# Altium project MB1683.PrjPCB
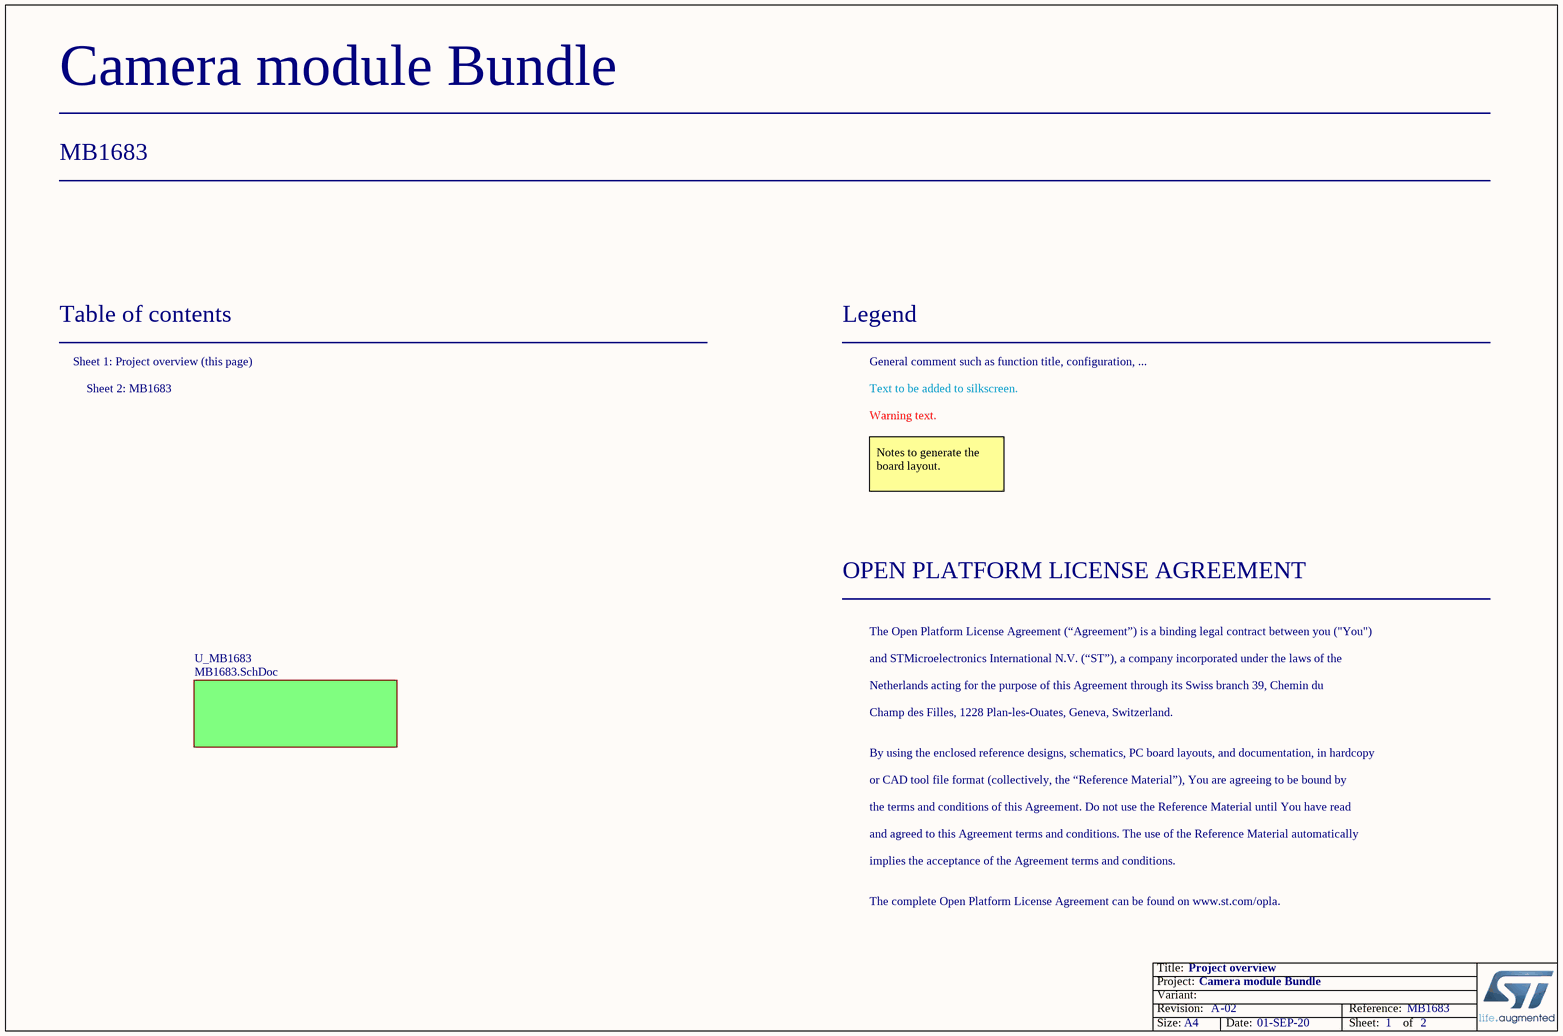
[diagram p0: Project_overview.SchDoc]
Board_Reference: MB1683; Board_PCB_Revision: A; Board_Name: Camera module Bundle; Board_Document_Date: 01-SEP-20; Board_BOM_Revision: 02; Board_Assembly_Revision: 02
2 sheets, 39 parts. Net scope: global (net labels, ports and power ports of the same name join across sheets).
Board file: MB1683.PcbDoc
Sheets:
  Project_overview.SchDoc
    U_MB1683 = MB1683.SchDoc

## Sheet Project_overview.SchDoc: Project overview
size A4; Date: Not used; ApprovedBy: Not used; CheckedBy: Not used; Author: Not used; CompanyName: STMicroelectronics; DrawnBy: Not used; Engineer: Not used; Organization: Not used; Address1: Not used; Address2: Not used; Address3: Not used; Address4: Not used; DocumentNumber: 1; Revision: Not used; SheetNumber: 1; SheetTotal: 2

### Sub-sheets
U_MB1683 = MB1683.SchDoc: no entries

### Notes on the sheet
- Table of contents
- Sheet 1: Project overview (this page)
- Legend
- General comment such as function title, configuration, ...
- Sheet 2: MB1683
- Text to be added to silkscreen.
- Warning text.
- Notes to generate the board layout.
- OPEN PLATFORM LICENSE AGREEMENT
- The Open Platform License Agreement (“Agreement”) is a binding legal contract between you ("You")
- and STMicroelectronics International N.V. (“ST”), a company incorporated under the laws of the
- Netherlands acting for the purpose of this Agreement through its Swiss branch 39, Chemin du
- Champ des Filles, 1228 Plan-les-Ouates, Geneva, Switzerland.
- By using the enclosed reference designs, schematics, PC board layouts, and documentation, in hardcopy
- or CAD tool file format (collectively, the “Reference Material”), You are agreeing to be bound by
- the terms and conditions of this Agreement. Do not use the Reference Material until You have read
- and agreed to this Agreement terms and conditions. The use of the Reference Material automatically
- implies the acceptance of the Agreement terms and conditions.
- The complete Open Platform License Agreement can be found on www.st.com/opla.

## Sheet MB1683.SchDoc: MB1683 TOP
size A4; Date: Not used; ApprovedBy: Not used; CheckedBy: Not used; Author: Not used; CompanyName: STMicroelectronics; DrawnBy: Not used; Engineer: Not used; Organization: Not used; Address1: Not used; Address2: Not used; Address3: Not used; Address4: Not used; DocumentNumber: Not used; Revision: Not used; SheetNumber: 2; SheetTotal: 2
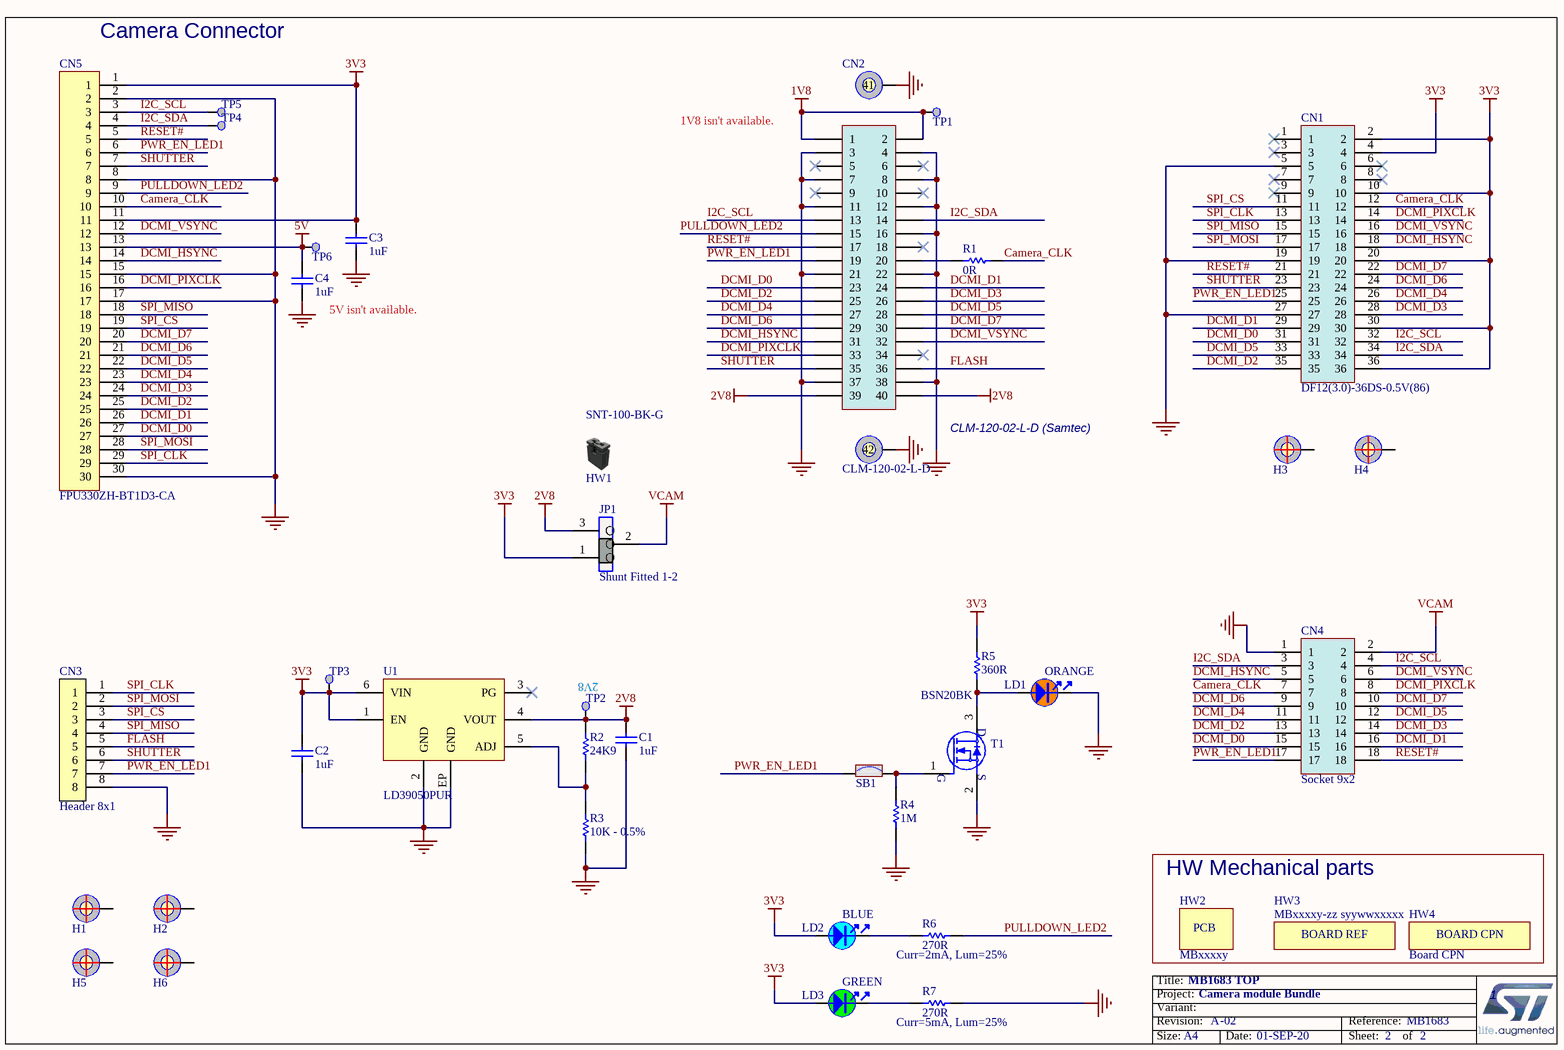
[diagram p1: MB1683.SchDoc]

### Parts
C1  value 1uF  [C0402]  (hidden comment: Capacitor)
C2  value 1uF  [C0402]  (hidden comment: Capacitor)
C3  value 1uF  [C0402]  (hidden comment: Capacitor)
C4  value 1uF  [C0402]  (hidden comment: Capacitor)
CN1  value DF12(3.0)-36DS-0.5V(86)  [CON_HRS_DF12-36DS-0.5V_86]  (hidden comment: DF12-36DS-0.5V)
CN2  value CLM-120-02-L-D  [CON_SAMTEC_CLM-120-02-L-D_Reverse-to-Camera]  (hidden comment: Socket 20x2 CLM_Reverse_for_camera)
CN3  Header 8x1  [CON_SAMTEC_TSW-108-07-X-S]
CN4  Socket 9x2  [CON_SAMTEC_SSW-109-01-X-D]
CN5  FPU330ZH-BT1D3-CA  [CON_TOWNES_FPU330ZH-BT1D3-CA_P050]
H1  POSITION HOLE  [NPTH_350]  (value not drawn)  (no BOM)
H2  POSITION HOLE  [NPTH_350]  (value not drawn)  (no BOM)
H3  POSITION HOLE  [NPTH_350]  (value not drawn)  (no BOM)
H4  POSITION HOLE  [NPTH_350]  (value not drawn)  (no BOM)
H5  POSITION HOLE  [NPTH_350]  (value not drawn)  (no BOM)
H6  POSITION HOLE  [NPTH_350]  (value not drawn)  (no BOM)
HW1  value SNT-100-BK-G  (hidden comment: Shunt Black 2.54mm)  (mechanical)
HW2  value MBxxxxy  (hidden comment: PCB)  (mechanical)
HW3  value MBxxxxy-zz syywwxxxxx  [STICKER_25X9]  (hidden comment: STICKER_BOARD_REF)  (no BOM)
HW4  value Board CPN  [STICKER_25X9]  (hidden comment: STICKER_BOARD_CPN)  (no BOM)
JP1  value Shunt Fitted 1-2  [CON_988-JIUBABA_313103S111116]  (hidden comment: Jumper_Header 3x1 Fitted 1-2)
LD1  value ORANGE  [LED_0603_OSRAM_LO-Q976-PS-25_ORANGE_1A2K_H0P8]  (hidden comment: LED_orange)
LD2  value BLUE  [LED_0603_VISHAY_VLMB1300-GS08_BLUE_1A2K_H0P8]  (hidden comment: LED_blue)
LD3  value GREEN  [LED_0603_VISHAY_VLMTG1300-GS08_GREEN_1A2K_H0P8]  (hidden comment: LED_green)
R1  value 0R  [R0402]  (hidden comment: Resistor)
R2  value 24K9  [R0402]  (hidden comment: Resistor)
R3  value 10K - 0.5%  [R0402]  (hidden comment: Resistor)
R4  value 1M  [R0402]  (hidden comment: Resistor)
R5  value 360R  [R0402]  (hidden comment: Resistor)
R6  value 270R  [R0402]  (hidden comment: Resistor)
R7  value 270R  [R0402]  (hidden comment: Resistor)
SB1  SB_ON  [SOLDER-BRIDGE_R0402-0R]  (value not drawn)
T1  value BSN20BK  [MOS_SOT23]  (hidden comment: BSN20)
TP1  Test Point  [TP_SMD_1MM]  (value not drawn)  (no BOM)
TP2  Test Point  [TP_SMD_1MM]  (value not drawn)  (no BOM)
TP3  Test Point  [TP_SMD_1MM]  (value not drawn)  (no BOM)
TP4  Test Point  [TP_SMD_1MM]  (value not drawn)  (no BOM)
TP5  Test Point  [TP_SMD_1MM]  (value not drawn)  (no BOM)
TP6  Test Point  [TP_SMD_1MM]  (value not drawn)  (no BOM)
U1  LD39050PUR  [ICC_DFN6-EPAD_3X3_P095]

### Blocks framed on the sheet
HW Mechanical parts: HW2-HW4

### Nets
1V8: CN2.1 CN2.2 TP1.1
2V8: C1.2 CN2.39 CN2.40 JP1.3 R2.2 TP2.1 U1.4(VOUT)
3V3: C2.2 C3.2 CN1.2 CN1.4 CN1.10 CN1.20 CN1.30 CN1.36 CN5.1 CN5.11 JP1.1 LD2.1 LD3.1 R5.2 TP3.1 U1.1(EN) U1.6(VIN)
5V: C4.2 CN5.13 TP6.1
GND: C1.1 C2.1 C3.1 C4.1 CN1.5 CN1.19 CN1.27 CN2.3 CN2.4 CN2.7 CN2.8 CN2.11 CN2.12 CN2.16 CN2.21 CN2.22 CN2.37 CN2.38 CN2.41 CN2.42 CN3.8 CN4.1 CN5.2 CN5.8 CN5.15 CN5.17 CN5.30 LD1.2 R3.1 R4.2 R7.2 T1.2(S) U1.2(GND) U1.EP(GND)
VCAM: CN4.2 JP1.2
Camera_CLK: CN1.12 CN4.7 CN5.10 R1.2
DCMI_D0: CN1.31 CN2.23 CN4.15 CN5.27
DCMI_D1: CN1.29 CN2.24 CN4.16 CN5.26
DCMI_D2: CN1.35 CN2.25 CN4.13 CN5.25
DCMI_D3: CN1.28 CN2.26 CN4.14 CN5.24
DCMI_D4: CN1.26 CN2.27 CN4.11 CN5.23
DCMI_D5: CN1.33 CN2.28 CN4.12 CN5.22
DCMI_D6: CN1.24 CN2.29 CN4.9 CN5.21
DCMI_D7: CN1.22 CN2.30 CN4.10 CN5.20
DCMI_HSYNC: CN1.18 CN2.31 CN4.5 CN5.14
DCMI_PIXCLK: CN1.14 CN2.33 CN4.8 CN5.16
DCMI_VSYNC: CN1.16 CN2.32 CN4.6 CN5.12
FLASH: CN2.36 CN3.5
I2C_SCL: CN1.32 CN2.13 CN4.4 CN5.3 TP5.1
I2C_SDA: CN1.34 CN2.14 CN4.3 CN5.4 TP4.1
PULLDOWN_LED2: CN2.15 CN5.9 R6.2
PWR_EN_LED1: CN1.25 CN2.19 CN3.7 CN4.17 CN5.6 SB1.1
RESET#: CN1.21 CN2.17 CN4.18 CN5.5
SHUTTER: CN1.23 CN2.35 CN3.6 CN5.7
SPI_CLK: CN1.13 CN3.1 CN5.29
SPI_CS: CN1.11 CN3.3 CN5.19
SPI_MISO: CN1.15 CN3.4 CN5.18
SPI_MOSI: CN1.17 CN3.2 CN5.28
NetCN2_20: CN2.20 R1.1
NetLD1_1: LD1.1 R5.1 T1.3(D)
NetLD2_2: LD2.2 R6.1
NetLD3_2: LD3.2 R7.1
NetR2_1: R2.1 R3.2 U1.5(ADJ)
NetR4_1: R4.1 SB1.2 T1.1(G)

Not connected (* = marked no-connect by the designer): CN1 1* 3* 6* 7* 8* 9*; CN2 5* 6* 9* 10* 18* 34*; H1 1; H2 1; H3 1; H4 1; H5 1; H6 1; U1 3(PG)*

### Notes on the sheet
- (near CN5) Camera Connector
- 1V8 isn't available.
- (near C4) 5V isn't available.
- (near CN2) CLM-120-02-L-D (Samtec)
- (near TP2) 2V8
- (near R6) Curr=2mA, Lum=25%
- 1
- (near R7) Curr=5mA, Lum=25%

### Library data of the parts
C1-C4 = MCD-01722: Capacitor, MLCC, 1uF, 10V, X5R, +/-10%, 0402, T=0.5mm; Manufacturer_Part_Number: CC0402KRX5R6BB105; Manufacturer: YAGEO; Alternate_Manufacturer_Part_Number: GCM155R71C104KA55D; Alternate_Manufacturer: MURATA; ECCN_US: EAR99; ECCN_EU: NEC; Provided_By: SUBCO
CN1 = MCD-02260: Receptacle, 18x2, 0.5mm, Straight,SMT, height 2.7mm, H=3.0MM; Part_Preference: Recommended; Part_Type: Connector; Manufacturer: HIROSE
CN2 = MCD-00138: Socket, 20x2, 1.0mm, VR, SMT, Height 2.26mm. Symbol & Footprint dedicated to MB1183 & MB1379 camera modules (not in line with Samtec datasheet); Part_Type: Connector; Provided_By: SUBCO; ECCN_US: EAR99; ECCN_EU: NEC
CN3 = MCD-00239: Header, 8x1, 2,54mm, VR, TH, Height 5.84mm/2.54mm; Part_Type: Connector; Manufacturer_Part_Number: TSW-108-07-G-S; Manufacturer: SAMTEC; Provided_By: SUBCO
CN4 = MCD-02157: Socket, 9x2, 2.54mm, VR, TH, Height 8.51mm/2.64mm, Standard insertion force.; Part_Type: Connector; Manufacturer_Part_Number: SSW-109-01-G-D; Manufacturer: SAMTEC; Order_Code_RS: 765-5717; Provided_By: SUBCO
CN5 = MCD-00326: Connector FFC/FPC ZIF 0.5mm 30 pins, Lower Contacts; Manufacturer: TOWNES; Provided_By: SUBCO
H1-H6 = MCD-01368: POSITION HOLE C3R5D3R5; Part_Type: Mechanical
HW1 = MCD-00043: SHUNT 2.54mm BLACK; Part_Type: Mechanical; Manufacturer: SAMTEC; Alternate_Manufacturer_Part_Number: 316102S111A; Alternate_Manufacturer: JIUBABA; Provided_By: SUBCO
HW2 = MCD-00216: PCB, xxxx for PCB number, Y for PCB revision; Part_Type: Mechanical; Provided_By: SUBCO
HW3 = MCD-00235: Sticker to mention board reference + serial number; Part_Type: Mechanical; Provided_By: SUBCO
HW4 = MCD-00547: Sticker to mention board CPN code; Part_Type: Mechanical; Provided_By: SUBCO
JP1 = MCD-01656: Header 3x1, 2.54mm, VR, TH, height 6 mm / 3 mm, total 11.6mm - Shunt Fitted 1-2 by default; Part_Type: Connector; Manufacturer_Part_Number: 313103S111116; Manufacturer: JIUBABA; Provided_By: SUBCO
LD1 = MCD-00590: LED Orange, 0603 SMD, Forward Voltage Min=1.6V, Max=2.4V; Part_Type: Display; Manufacturer_Part_Number: LO Q976-PS-25; Manufacturer: OSRAM OPTO SEMICONDUCTORS; Alternate_Manufacturer_Part_Number: VLMO1300-GS08; Alternate_Manufacturer: VISHAY SEMICONDUCTOR OPTO DIVISION; Provided_By: SUBCO
LD2 = MCD-00585: LED Blue, 0603 SMD, Forward Voltage Min=2,8V, Max=3,8V; Part_Type: Display; Manufacturer_Part_Number: LB Q39G-L2OO-35-1; Manufacturer: OSRAM OPTO SEMICONDUCTORS; Alternate_Manufacturer_Part_Number: 19-217-BHC-ZL1M2RY-3T-V4; Alternate_Manufacturer: EVERLIGHT; Order_Code_RS: 9148643; Provided_By: SUBCO
LD3 = MCD-00588: LED Green, 0603 SMD, Forward Voltage Typ=2V, Max=2.5V; Part_Type: Display; Manufacturer_Part_Number: LG Q396-PS-35; Manufacturer: OSRAM OPTO SEMICONDUCTORS; Alternate_Manufacturer_Part_Number: VLMTG1300-GS08; Alternate_Manufacturer: VISHAY SEMICONDUCTOR OPTO DIVISION; Provided_By: SUBCO; Order_Code_RS: 7730452
R1 = MCD-00052: Resistor,0R,0402,5%,1/16W; Manufacturer_Part_Number: RC0402JR-070RL; Manufacturer: YAGEO; Alternate_Manufacturer_Part_Number: RT0402FRE07100KL; ECCN_US: EAR99; ECCN_EU: NEC; Provided_By: SUBCO; Order_Code_RS: 618-5804
R2 = MCD-02207: Resistor,24K9,0402,1%,1/10W; Manufacturer_Part_Number: RC0402FR-0724K9L; Manufacturer: YAGEO; Part_Preference: Recommended; ECCN_US: EAR99; ECCN_EU: NEC; Provided_By: SUBCO; Order_Code_RS: 198-7718
R3 = MCD-01816: Resistor, 10K, 0402, 0.5%, 1/16W,±100ppm/°C; Manufacturer_Part_Number: RC0402DR-0710KL; Manufacturer: YAGEO; Alternate_Manufacturer_Part_Number: RT0402FRE07100KL; ECCN_US: EAR99; ECCN_EU: NEC; Provided_By: SUBCO
R4 = MCD-00182: Resistor,1M,0402,1%,1/16W; Manufacturer_Part_Number: RC0402FR-071ML; Manufacturer: YAGEO; Alternate_Manufacturer_Part_Number: RT0402FRE07100KL; BMS_Part_Number: 9131778; Provided_By: SUBCO; ECCN_US: EAR99; ECCN_EU: NEC; Order_Code_RS: 618-6194
R5 = MCD-00461: Resistor,360R,0402,1%,1/16W; Manufacturer_Part_Number: RC0402FR-07360RL; Manufacturer: YAGEO; Alternate_Manufacturer_Part_Number: RT0402FRE07100KL; Provided_By: SUBCO; ECCN_EU: NEC; ECCN_US: EAR99
R6 R7 = MCD-00441: Resistor,270R,0402,1%,1/16W; Manufacturer_Part_Number: RC0402FR-07270RL; Manufacturer: YAGEO; Alternate_Manufacturer_Part_Number: RT0402FRE07100KL; Provided_By: SUBCO; ECCN_US: EAR99; ECCN_EU: NEC
SB1 = MCD-01618: Solder Bridge 0402 ON; Part_Type: Misc; Manufacturer_Part_Number: RC0402JR-070RL; Manufacturer: YAGEO; Part_Preference: Recommended; Provided_By: SUBCO; Order_Code_RS: 618-5804
T1 = MCD-01969: Transistor, N-channel enhancement mode field-effect transistor; Manufacturer: NEXPERIA; ECCN_US: EAR99; ECCN_EU: NEC; Provided_By: SUBCO; Order_Code_RS: 136-4845
TP1-TP6 = MCD-00074: Test Point 1mm; Part_Type: Mechanical
U1 = MCD-02161: Low quiescent current and low noise voltage regulators; Part_Type: IC; Manufacturer: STMICROELECTRONICS; Order_Code_RS: 880-5317; ECCN_US: EAR99; ECCN_EU: NEC; Provided_By: SUBCO with ST control

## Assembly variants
CAMS: not fitted C4 R1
